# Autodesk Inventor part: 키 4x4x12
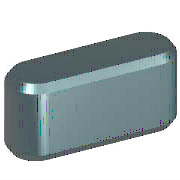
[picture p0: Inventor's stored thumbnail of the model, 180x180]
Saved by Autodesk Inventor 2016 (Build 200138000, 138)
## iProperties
IsCustomPart: 1
Created: 2012-02
Part Number: 키 4x4x12
Material: 강철, 연강
Description: 키 및 해당 키홈
Document SubType Name: Modeling
Standard: KS B 1311
Designer: mduedu
Standards Organization: KS
Language: ko-KR
Size Designation: 4 x 4 x 12
Categories: <MemberInstance><Categories><Category DisplayName="샤프트 부품" InternalName="7f7aeb1f-a693-4053-b835-cee3144e0d98" Mnemonic="SHFT"><Category DisplayName="키" Interna
Density: 7.85 g/cm^3
Appearance: 노란색
Mass: 1.38563 g
Surface Area: 1.94869 cm^2
Volume: 0.176513 cm^3
Author: mduedu
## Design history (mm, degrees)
workplane "Work Plane1"
workplane "Work Plane2"
sketch "스케치1"
  geometry: L1 (2, 2)-(10, 2); L2 (10, -2)-(2, -2); L3 (0, 9.4)-(0, -7.4) reference; L4 (-5, 0)-(30, 0) reference; L5 (12, 0)-(12, 7); A1 r 2 centre (2, 0) between (2, 2) and (2, -2); A2 r 2 centre (10, 0) between (10, -2) and (10, 2)
  constraints: 6 end point, 5 point on circle, 4 tangent, 3 point on line, 2 centre point, 1 horizontal, 1 parallel, 1 perpendicular
  dimensions: "d0" = 2 radius of A1 (= 0.5 x PB); "d13" = 2 radius of A2 (= 0.5 x PB); "d14" = 12 distance between parallel lines of L5 L3 (= NLG)
extrude "본체1" new body sketch "스케치1" taper "d3" = 0 deg; stored distance "d4" = 10
workplane "Work Plane3"
body "Solid1"
chamfer "모따기1" distance "d8" = 0.25 (= PHH); stored, may be unused: second distance "d9" = 0.25 (= PHH), angle "d15" = 45 deg
other parameters: "d1" = -2.5 (= -PNT), "d2" = 1.5 (= PH - PNT), "NLG" = 12 [user parameter; used in 3 equation terms], "PB" = 4 [user parameter; used in 2 equation terms], "PNT" = 2.5 [user parameter; used in 2 equation terms], "PH" = 4 [user parameter; used in 1 equation term], "PHH" = 0.25 [user parameter; used in 2 equation terms], "d10" = 0, "d16" = 0, "d17" = 0, "d18" = 0, "PLB2" = 12 (= NLG) [user parameter], "WDMAX" = 12 [user parameter], "PLB1" = 12 (= NLG) [user parameter], "RR" = 0.08 [user parameter], "PUEB" = 1.8 [user parameter]
